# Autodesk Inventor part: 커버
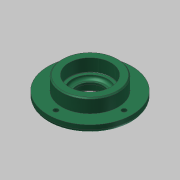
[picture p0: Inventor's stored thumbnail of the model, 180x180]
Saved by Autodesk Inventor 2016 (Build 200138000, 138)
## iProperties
Company: 한국ATC센터
Created: 2014-10
Part Number: 커버
Document SubType Name: Modeling
Designer: KYOUNG IL JANG
Density: 7.86 g/cm^3
Mass: 351.567 g
Surface Area: 161.165 cm^2
Volume: 44.7286 cm^3
Material: 알루미늄 6061
Appearance: 알루미늄 - 평지
Author: KYOUNG IL JANG
Revision Number: 1
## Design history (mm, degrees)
sketch "스케치1"
  geometry: C1 r 40 at (0, 0); 1 further point
  constraints: 1 centre point, 1 coincident
  dimensions: "d0" = 80 diameter of C1
extrude "돌출1" new body sketch "스케치1" distance "d1" = 7; taper "d2" = 0 deg
sketch "스케치2"
  geometry: C1 r 27 at (0, 0); 1 further point
  constraints: 1 centre point, 1 coincident
  dimensions: "d3" = 54 diameter of C1
extrude "돌출2" join sketch "스케치2" distance "d4" = 13; taper "d5" = 0 deg
sketch "스케치3"
  geometry: C1 r 20 at (0, 0); 1 further point
  constraints: 1 centre point, 1 coincident
  dimensions: "d6" = 40 diameter of C1
extrude "돌출3" join sketch "스케치3" distance "d7" = 5; taper "d8" = 0 deg
hole "구멍1" diameter "d11" = 25; stored, may be unused: countersink angle "d15" = 90 deg, drill point angle "d17" = 118 deg; dims "d9" = 10, "d10" = 10, "d12" = 6, "d13" = 32, "d14" = 8.3, "d16" = 8
hole "구멍2" diameter "d20" = 34; stored, may be unused: countersink angle "d24" = 90 deg, drill point angle "d26" = 0 deg; dims "d18" = 10, "d19" = 10, "d21" = 6, "d22" = 40, "d23" = 12, "d25" = 3
fillet "모깎기2" dims "d34" = 3
fillet "모깎기1" dims "d27" = 0.3
chamfer "모따기1" distance "d28" = 1; stored, may be unused: second distance "d29" = 2, angle "d30" = 45 deg
chamfer "모따기2" distance "d31" = 1.2; stored, may be unused: second distance "d32" = 2, angle "d33" = 30 deg
sketch "스케치4" dims "d35" = 65
  geometry: 3 further points
  constraints: 2 horizontal alignment, 1 coincident, 2 other
hole "구멍3" sketch "스케치4" at (32.5, 0) diameter "d36" = 4.5; stored, may be unused: countersink angle "d40" = 90 deg, drill point angle "d42" = 118 deg; dims "d37" = 6, "d38" = 8, "d39" = 4.4, "d41" = 13
node "솔리드1"
pattern_circular "원형 패턴1" dims angle "d44" = 360 deg
